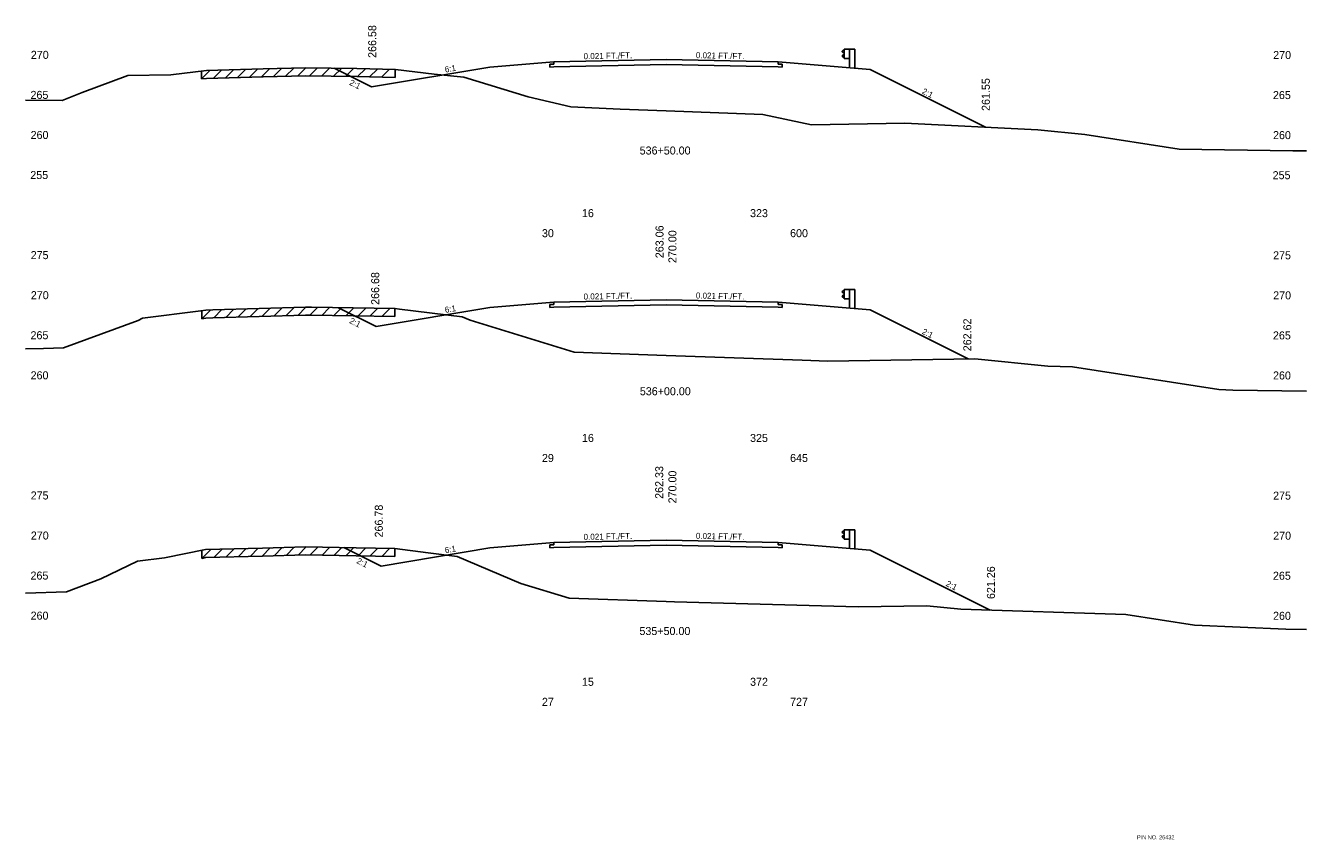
# Model space of a CAD drawing. Extents: x 2967 to 4323, y -3677 to -817.
# Drawn here: x 3555.3 to 3715.3, y -2772.2 to -2670.6 of the extents above; entities that cross this region are included whole.
import ezdxf

# ---------------------------------------------------------------- set-up
doc = ezdxf.new("R2010")
doc.units = 0
for name, color, linetype in [('Level 1', 7, 'Continuous'), ('Level 10', 7, 'Continuous'), ('Level 11', 7, 'Continuous'), ('Level 12', 7, 'Continuous'), ('Level 20', 7, 'Continuous'), ('Level 24', 7, 'Continuous'), ('Level 3', 7, 'Continuous'), ('Level 32', 7, 'Continuous'), ('Level 33', 7, 'Continuous'), ('Level 59', 7, 'Continuous'), ('Level 6', 7, 'Continuous'), ('Level 60', 7, 'Continuous'), ('Level 61', 7, 'Continuous'), ('Level 7', 7, 'Continuous')]:
    doc.layers.add(name, color=color, linetype=linetype)

msp = doc.modelspace()

# ---------------------------------------------------------------- linework, layer by layer
at = {"layer": 'Level 11'}
for p, q in [((3621.35, -2675.13), (3621.35, -2675.43)), ((3649.35, -2675.43), (3649.35, -2675.13)), ((3621.35, -2675.43), (3620.85, -2675.44)), ((3620.85, -2675.44), (3620.85, -2675.78)), ((3620.85, -2675.78), (3621.35, -2675.77)), ((3649.85, -2675.44), (3649.35, -2675.43)), ((3649.35, -2675.77), (3649.85, -2675.78)), ((3649.85, -2675.78), (3649.85, -2675.44)), ((3621.35, -2705.43), (3620.85, -2705.44)), ((3620.85, -2705.44), (3620.85, -2705.78)), ((3621.35, -2705.13), (3621.35, -2705.43)), ((3649.35, -2705.43), (3649.35, -2705.13)), ((3649.85, -2705.44), (3649.35, -2705.43)), ((3649.85, -2705.78), (3649.85, -2705.44)), ((3620.85, -2705.78), (3621.35, -2705.77)), ((3649.35, -2705.77), (3649.85, -2705.78)), ((3621.35, -2735.43), (3620.85, -2735.44)), ((3620.85, -2735.44), (3620.85, -2735.78)), ((3620.85, -2735.78), (3621.35, -2735.77)), ((3621.35, -2735.13), (3621.35, -2735.43)), ((3649.35, -2735.43), (3649.35, -2735.13)), ((3649.85, -2735.44), (3649.35, -2735.43)), ((3649.35, -2735.77), (3649.85, -2735.78)), ((3649.85, -2735.78), (3649.85, -2735.44))]:
    msp.add_line(p, q, dxfattribs=at)
at = {"layer": 'Level 12'}
for p, q in [((3635.35, -2675.48), (3621.35, -2675.77)), ((3649.35, -2675.77), (3635.35, -2675.48)), ((3635.35, -2705.48), (3621.35, -2705.77)), ((3649.35, -2705.77), (3635.35, -2705.48)), ((3635.35, -2735.48), (3621.35, -2735.77)), ((3649.35, -2735.77), (3635.35, -2735.48))]:
    msp.add_line(p, q, dxfattribs=at)
at = {"layer": 'Level 24'}
for p, q in [((3657.62, -2674.72), (3657.62, -2673.55)), ((3657.62, -2673.55), (3658.28, -2673.55)), ((3658.28, -2673.55), (3658.28, -2675.88)), ((3658.28, -2673.55), (3658.95, -2673.55)), ((3658.95, -2673.55), (3658.95, -2675.93)), ((3657.62, -2673.62), (3657.35, -2673.82)), ((3657.35, -2673.82), (3657.35, -2673.87)), ((3657.35, -2673.87), (3657.62, -2674.07)), ((3657.35, -2674.39), (3657.62, -2674.19)), ((3657.35, -2674.44), (3657.35, -2674.39)), ((3657.62, -2674.64), (3657.35, -2674.44)), ((3657.62, -2674.72), (3658.29, -2674.72)), ((3657.62, -2703.62), (3657.35, -2703.82)), ((3657.35, -2703.82), (3657.35, -2703.87)), ((3657.35, -2703.87), (3657.62, -2704.07)), ((3657.62, -2704.72), (3657.62, -2703.55)), ((3657.62, -2703.55), (3658.28, -2703.55)), ((3658.28, -2703.55), (3658.28, -2705.88)), ((3658.28, -2703.55), (3658.95, -2703.55)), ((3658.95, -2703.55), (3658.95, -2705.93)), ((3657.35, -2704.39), (3657.62, -2704.19)), ((3657.35, -2704.44), (3657.35, -2704.39)), ((3657.62, -2704.64), (3657.35, -2704.44)), ((3657.62, -2704.72), (3658.29, -2704.72)), ((3657.62, -2733.62), (3657.35, -2733.82)), ((3657.35, -2733.82), (3657.35, -2733.87)), ((3657.35, -2733.87), (3657.62, -2734.07)), ((3657.35, -2734.39), (3657.62, -2734.19)), ((3657.35, -2734.44), (3657.35, -2734.39)), ((3657.62, -2734.72), (3657.62, -2733.55)), ((3657.62, -2733.55), (3658.28, -2733.55)), ((3658.28, -2733.55), (3658.28, -2735.88)), ((3658.28, -2733.55), (3658.95, -2733.55)), ((3658.95, -2733.55), (3658.95, -2735.93)), ((3657.62, -2734.64), (3657.35, -2734.44)), ((3657.62, -2734.72), (3658.29, -2734.72))]:
    msp.add_line(p, q, dxfattribs=at)
at = {"layer": 'Level 59'}
for p, q in [((3621.35, -2675.13), (3635.35, -2674.84)), ((3635.35, -2674.84), (3649.35, -2675.13)), ((3621.35, -2705.13), (3635.35, -2704.84)), ((3635.35, -2704.84), (3649.35, -2705.13)), ((3621.35, -2735.13), (3635.35, -2734.84)), ((3635.35, -2734.84), (3649.35, -2735.13))]:
    msp.add_line(p, q, dxfattribs=at)
at = {"layer": 'Level 6'}
for p, q in [((3613.35, -2675.8), (3621.35, -2675.13)), ((3649.35, -2675.13), (3660.85, -2676.09)), ((3613.35, -2705.8), (3621.35, -2705.13)), ((3649.35, -2705.13), (3660.85, -2706.09)), ((3613.35, -2735.8), (3621.35, -2735.13)), ((3649.35, -2735.13), (3660.85, -2736.09))]:
    msp.add_line(p, q, dxfattribs=at)
at = {"layer": 'Level 60'}
for p, q in [((3568.12, -2676.85), (3573.49, -2676.74)), ((3573.49, -2676.74), (3577.94, -2676.2)), ((3577.94, -2676.2), (3585.02, -2675.99)), ((3585.02, -2675.99), (3590.3, -2675.88)), ((3590.3, -2675.88), (3596.71, -2675.98)), ((3596.71, -2675.98), (3601.56, -2676.07)), ((3601.56, -2676.07), (3606.38, -2676.66)), ((3606.38, -2676.66), (3610.08, -2677.05)), ((3562.43, -2678.95), (3568.12, -2676.85)), ((3610.08, -2677.05), (3618.11, -2679.52)), ((3555.35, -2679.93), (3559.92, -2679.96)), ((3559.92, -2679.96), (3562.43, -2678.95)), ((3618.11, -2679.52), (3623.46, -2680.76)), ((3623.46, -2680.76), (3629.61, -2681.06)), ((3629.61, -2681.06), (3635.35, -2681.26)), ((3635.35, -2681.26), (3647.43, -2681.69)), ((3647.43, -2681.69), (3653.54, -2682.98)), ((3653.54, -2682.98), (3665.17, -2682.8)), ((3665.17, -2682.8), (3681.79, -2683.61)), ((3681.79, -2683.61), (3687.66, -2684.2)), ((3687.66, -2684.2), (3699.47, -2686.02)), ((3699.47, -2686.02), (3713.64, -2686.23)), ((3713.64, -2686.23), (3715.35, -2686.25)), ((3569.41, -2707.4), (3569.97, -2707.13)), ((3569.97, -2707.13), (3577.24, -2706.23)), ((3577.24, -2706.23), (3577.86, -2706.11)), ((3577.86, -2706.11), (3578.73, -2706.09)), ((3578.73, -2706.09), (3590.3, -2705.75)), ((3590.3, -2705.75), (3591.08, -2705.76)), ((3591.08, -2705.76), (3601.53, -2705.93)), ((3601.53, -2705.93), (3602.05, -2706)), ((3602.05, -2706), (3609.88, -2706.95)), ((3609.88, -2706.95), (3610.89, -2707.38)), ((3560.1, -2710.84), (3569.41, -2707.4)), ((3610.89, -2707.38), (3623.87, -2711.37)), ((3555.35, -2710.95), (3557.57, -2710.93)), ((3557.57, -2710.93), (3560.1, -2710.84)), ((3623.87, -2711.37), (3635.35, -2711.78)), ((3635.35, -2711.78), (3652.37, -2712.39)), ((3652.37, -2712.39), (3655.58, -2712.48)), ((3655.58, -2712.48), (3673.93, -2712.21)), ((3673.93, -2712.21), (3683.06, -2713.12)), ((3683.06, -2713.12), (3686.12, -2713.22)), ((3686.12, -2713.22), (3704.4, -2716.05)), ((3704.4, -2716.05), (3706.16, -2716.13)), ((3706.16, -2716.13), (3715.35, -2716.24)), ((3577.81, -2736.02), (3584.96, -2735.83)), ((3584.96, -2735.83), (3590.31, -2735.67)), ((3590.31, -2735.67), (3596.65, -2735.78)), ((3596.65, -2735.78), (3601.46, -2735.86)), ((3601.46, -2735.86), (3605.62, -2736.42)), ((3564.76, -2739.68), (3569.32, -2737.46)), ((3569.32, -2737.46), (3572.68, -2737.04)), ((3572.68, -2737.04), (3577.81, -2736.02)), ((3605.62, -2736.42), (3609.24, -2736.86)), ((3609.24, -2736.86), (3617.23, -2740.23)), ((3560.46, -2741.27), (3564.76, -2739.68)), ((3617.23, -2740.23), (3623.24, -2742.07)), ((3555.35, -2741.46), (3560.46, -2741.27)), ((3623.24, -2742.07), (3635.35, -2742.51)), ((3635.35, -2742.51), (3636.43, -2742.55)), ((3636.43, -2742.55), (3659.37, -2743.17)), ((3659.37, -2743.17), (3667.93, -2743.05)), ((3667.93, -2743.05), (3672.19, -2743.47)), ((3672.19, -2743.47), (3692.78, -2744.1)), ((3692.78, -2744.1), (3701.37, -2745.43)), ((3701.37, -2745.43), (3712.78, -2745.95)), ((3712.78, -2745.95), (3715.35, -2745.98))]:
    msp.add_line(p, q, dxfattribs=at)
at = {"layer": 'Level 61'}
for p, q in [((3578.41, -2676.18), (3577.32, -2677.27)), ((3577.32, -2676.27), (3577.32, -2677.27)), ((3579.85, -2676.14), (3578.82, -2677.17)), ((3581.35, -2676.1), (3580.32, -2677.13)), ((3582.85, -2676.05), (3581.82, -2677.08)), ((3584.35, -2676.01), (3583.32, -2677.04)), ((3585.84, -2675.97), (3584.82, -2677)), ((3587.34, -2675.94), (3586.32, -2676.96)), ((3588.84, -2675.91), (3587.82, -2676.93)), ((3590.34, -2675.88), (3589.32, -2676.9)), ((3591.8, -2675.9), (3590.82, -2676.89)), ((3593.3, -2675.93), (3592.32, -2676.91)), ((3594.8, -2675.95), (3593.82, -2676.93)), ((3596.3, -2675.97), (3595.32, -2676.96)), ((3597.8, -2676), (3596.82, -2676.98)), ((3599.3, -2676.03), (3598.32, -2677.01)), ((3600.8, -2676.06), (3599.82, -2677.04)), ((3601.51, -2677.07), (3601.51, -2676.07)), ((3577.32, -2677.27), (3577.94, -2677.2)), ((3577.94, -2677.2), (3585.02, -2676.99)), ((3585.02, -2676.99), (3590.3, -2676.88)), ((3590.3, -2676.88), (3596.71, -2676.98)), ((3596.71, -2676.98), (3601.51, -2677.07)), ((3578.47, -2706.09), (3577.35, -2707.21)), ((3577.35, -2706.21), (3577.35, -2707.21)), ((3577.35, -2707.21), (3577.86, -2707.11)), ((3577.86, -2707.11), (3578.73, -2707.09)), ((3578.73, -2707.09), (3590.3, -2706.75)), ((3579.88, -2706.05), (3578.85, -2707.08)), ((3581.38, -2706.01), (3580.35, -2707.04)), ((3582.88, -2705.97), (3581.85, -2707)), ((3584.38, -2705.92), (3583.35, -2706.95)), ((3585.88, -2705.88), (3584.85, -2706.91)), ((3587.38, -2705.84), (3586.35, -2706.87)), ((3588.88, -2705.79), (3587.85, -2706.82)), ((3590.37, -2705.75), (3589.35, -2706.78)), ((3590.3, -2706.75), (3591.08, -2706.76)), ((3591.83, -2705.78), (3590.85, -2706.76)), ((3591.08, -2706.76), (3601.49, -2706.93)), ((3593.33, -2705.8), (3592.35, -2706.78)), ((3594.83, -2705.82), (3593.85, -2706.81)), ((3596.33, -2705.85), (3595.35, -2706.83)), ((3597.83, -2705.87), (3596.85, -2706.86)), ((3599.33, -2705.9), (3598.35, -2706.88)), ((3600.83, -2705.92), (3599.85, -2706.9)), ((3601.49, -2706.93), (3601.49, -2705.93)), ((3579.91, -2735.96), (3578.88, -2736.99)), ((3581.41, -2735.92), (3580.38, -2736.95)), ((3582.91, -2735.88), (3581.88, -2736.91)), ((3584.41, -2735.84), (3583.38, -2736.87)), ((3585.91, -2735.8), (3584.88, -2736.83)), ((3587.41, -2735.75), (3586.38, -2736.78)), ((3588.91, -2735.71), (3587.88, -2736.74)), ((3590.41, -2735.67), (3589.38, -2736.7)), ((3591.86, -2735.7), (3590.88, -2736.68)), ((3593.36, -2735.72), (3592.38, -2736.71)), ((3594.86, -2735.75), (3593.88, -2736.73)), ((3596.36, -2735.77), (3595.38, -2736.76)), ((3597.86, -2735.8), (3596.88, -2736.78)), ((3599.36, -2735.82), (3598.38, -2736.81)), ((3600.86, -2735.85), (3599.88, -2736.83)), ((3601.46, -2736.86), (3601.46, -2735.86)), ((3578.49, -2736), (3577.38, -2737.11)), ((3577.38, -2736.11), (3577.38, -2737.11)), ((3577.38, -2737.11), (3577.81, -2737.02)), ((3577.81, -2737.02), (3584.96, -2736.83)), ((3584.96, -2736.83), (3590.31, -2736.67)), ((3590.31, -2736.67), (3596.65, -2736.78)), ((3596.65, -2736.78), (3601.46, -2736.86))]:
    msp.add_line(p, q, dxfattribs=at)
at = {"layer": 'Level 7'}
for p, q in [((3593.89, -2675.94), (3598.55, -2678.27)), ((3598.55, -2678.27), (3613.35, -2675.8)), ((3660.85, -2676.09), (3675.25, -2683.29)), ((3594.45, -2705.82), (3599.15, -2708.17)), ((3599.15, -2708.17), (3613.35, -2705.8)), ((3660.85, -2706.09), (3673.1, -2712.22)), ((3595.12, -2735.75), (3599.75, -2738.07)), ((3599.75, -2738.07), (3613.35, -2735.8)), ((3660.85, -2736.09), (3675.84, -2743.59))]:
    msp.add_line(p, q, dxfattribs=at)

# ---------------------------------------------------------------- texts
at = {"layer": 'Level 1'}
for s, p in [('16', (3624.85, -2694.52)), ('323', (3645.85, -2694.52)), ('30', (3619.85, -2697.02)), ('600', (3650.85, -2697.02)), ('16', (3624.85, -2722.58)), ('325', (3645.85, -2722.58)), ('29', (3619.85, -2725.08)), ('645', (3650.85, -2725.08)), ('15', (3624.85, -2753.02)), ('372', (3645.85, -2753.02)), ('27', (3619.85, -2755.52)), ('727', (3650.85, -2755.52))]:
    msp.add_text(s, height=1, dxfattribs=at).set_placement(p)
at = {"layer": 'Level 10'}
for s, p in [('536+50.00', (3632.06, -2686.7)), ('536+00.00', (3632.08, -2716.75)), ('535+50.00', (3632.03, -2746.68))]:
    msp.add_text(s, height=1, dxfattribs=at).set_placement(p)
for s, p in [('263.06', (3635.04, -2699.64)), ('262.33', (3635, -2729.68))]:
    msp.add_text(s, height=1, rotation=90, dxfattribs=at).set_placement(p)
at = {"layer": 'Level 20'}
msp.add_text('PIN NO. 26432', height=0.5, dxfattribs=at).set_placement((3694.19, -2772.18))
at = {"layer": 'Level 3'}
for s, p in [(' 270', (3555.63, -2674.76)), (' 270', (3710.83, -2674.78)), (' 265', (3555.59, -2679.76)), (' 265', (3710.8, -2679.78)), (' 260', (3555.6, -2684.76)), (' 260', (3710.81, -2684.78)), (' 255', (3555.56, -2689.76)), (' 255', (3710.76, -2689.78)), (' 275', (3555.61, -2699.76)), (' 275', (3710.82, -2699.78)), (' 270', (3555.63, -2704.76)), (' 270', (3710.83, -2704.78)), (' 265', (3555.59, -2709.76)), (' 265', (3710.8, -2709.78)), (' 260', (3555.6, -2714.76)), (' 260', (3710.81, -2714.78)), (' 275', (3555.61, -2729.76)), (' 275', (3710.82, -2729.78)), (' 270', (3555.63, -2734.76)), (' 270', (3710.83, -2734.78)), (' 265', (3555.59, -2739.76)), (' 265', (3710.8, -2739.78)), (' 260', (3555.6, -2744.76)), (' 260', (3710.81, -2744.78))]:
    msp.add_text(s, height=1, dxfattribs=at).set_placement(p)
at = {"layer": 'Level 32'}
for s, rotation, p in [('0.021 FT./FT.', 1.1916, (3625.06, -2674.81)), ('0.021 FT./FT.', 358.8084, (3639.07, -2674.67)), ('6:1', 9.4623, (3607.78, -2676.47)), ('2:1', 333.435, (3595.72, -2677.96)), ('2:1', 333.435, (3667.25, -2679.05)), ('0.021 FT./FT.', 1.1916, (3625.06, -2704.81)), ('0.021 FT./FT.', 358.8084, (3639.07, -2704.67)), ('6:1', 9.4623, (3607.78, -2706.47)), ('2:1', 333.435, (3595.73, -2707.7)), ('2:1', 333.435, (3667.25, -2709.05)), ('0.021 FT./FT.', 1.1916, (3625.06, -2734.81)), ('0.021 FT./FT.', 358.8084, (3639.07, -2734.67)), ('6:1', 9.4623, (3607.78, -2736.47)), ('2:1', 333.435, (3596.62, -2737.67)), ('2:1', 333.435, (3670.24, -2740.51))]:
    msp.add_text(s, height=0.75, rotation=rotation, dxfattribs=at).set_placement(p)
at = {"layer": 'Level 33'}
for s, p in [('266.58', (3599.15, -2674.64)), ('261.55', (3675.8, -2681.26)), ('266.68', (3599.52, -2705.47)), ('262.62', (3673.49, -2711.26)), ('266.78', (3599.97, -2734.5)), ('621.26', (3676.44, -2742.19))]:
    msp.add_text(s, height=1, rotation=90, dxfattribs=at).set_placement(p)
at = {"layer": 'Level 59'}
for p in [(3636.65, -2700.62), (3636.65, -2730.62)]:
    msp.add_text(' 270.00', height=1, rotation=90, dxfattribs=at).set_placement(p)

doc.saveas('drawing.dxf')
